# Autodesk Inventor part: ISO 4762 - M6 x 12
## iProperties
Comments: To add or edit properties for Autodesk Inventor files, use iProperties.
Created: 2004-08
Part Number: ISO 4762 - M6 x 12
Vendor: Autodesk Inc.
Document SubType Name: Modeling
Designer: John Blackburn
Material: Default
Description: Hexagon Socket Head Cap Screw
Standard: ISO 4762
Alert: To add or edit properties for Autodesk Inventor files, use iProperties.
Control State: 0
Master: False
Checked Out: False
Shininess: 64.0
Length Units: 11269
Angle Units: 11279
Time Units: 11290
Mass Units: 11283
Length Display Precision: 3
Angle Display Precision: 2
Compacted: True
EGR: 1
Density: 0.0
Volumn: 0.0
Area: 0.0
PropertySet Name: Model Information
Author: John Blackburn
Revision Number: 8
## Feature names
1. Body [Revolution]
2. Slot [Extrusion]
3. Fillet1
4. Chamfer1
